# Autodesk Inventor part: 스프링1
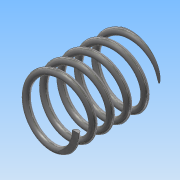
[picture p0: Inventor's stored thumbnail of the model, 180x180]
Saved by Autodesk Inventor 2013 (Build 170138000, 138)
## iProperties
Created: 2016-10
Part Number: 스프링1
Material: 강철, 탄소
Document SubType Name: Modeling
Designer: Administrator
Mass: 4.26354 g
Surface Area: 11.2836 cm^2
Volume: 0.541746 cm^3
Density: 7.87 g/cm^3
Author: Administrator
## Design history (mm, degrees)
sketch "스케치1"
  geometry: L1 (0, 0)-(0, 16.67); L2 (0, 16.67)-(25, 16.67); C1 r 1 at (9, 0)
  constraints: 4 end point, 1 centre point, 1 horizontal alignment, 1 perpendicular, 1 vertical
  dimensions: "d0" = 16.66987 distance of L1.start L1.end (derived); "d1" = 25 distance of L1.end L2.end; "d2" = 2 diameter of C1; "d3" = 18 diameter of C1.centre L1
feature "코일1" sketch "스케치1" pitch "d4" = 10; turns "d6" = 5; dims "d5" = 27, "d7" = 0, angle "d8" = 90 deg, angle "d9" = 90 deg, "d10" = 0, "d11" = 0
sketch "스케치2"
  geometry: L1 (16.67, 12)-(0, 12); L2 (0, 12)-(0, -12); L3 (0, -12)-(16.67, -12); L4 (16.67, -12)-(16.67, 12); 2 further points
  constraints: 8 end point, 2 parallel, 1 coincident, 1 horizontal, 1 midpoint, 1 perpendicular
  dimensions: "d12" = 16.66987 distance of L1.start L1.end (derived); "d14" = 24 distance of L3.end L1.start
extrude "돌출1" sketch "스케치2" stored distance "d15" = 0; taper "d16" = 0 deg
node "솔리드1"
